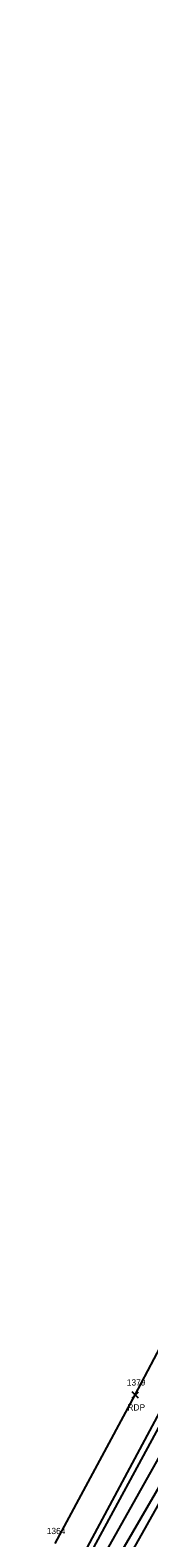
# Model space of a CAD drawing. Extents: x 1483143 to 1488182, y 802902 to 807581.
# Drawn here: x 1487393.8 to 1487426.2, y 805492.2 to 805974.5 of the extents above; entities that cross this region are included whole.
import ezdxf

# ---------------------------------------------------------------- set-up
doc = ezdxf.new("R2010")
doc.units = 0
for name, color, linetype in [('LELB', 7, 'Continuous'), ('P_A', 7, 'Continuous'), ('P_I', 7, 'Continuous'), ('P_TIC', 7, 'Continuous'), ('PET', 7, 'Continuous'), ('PSP', 7, 'Continuous')]:
    doc.layers.add(name, color=color, linetype=linetype)

msp = doc.modelspace()

# ---------------------------------------------------------------- linework, layer by layer
at = {"layer": 'LELB'}
for points in [[(1487406.66, 805485.41), (1487431.45, 805531.24), (1487454.84, 805575.74), (1487473.75, 805612.05), (1487489.43, 805642.37), (1487507.64, 805678.53), (1487524.82, 805711.39), (1487541.86, 805746.09), (1487557.67, 805776.44), (1487575.49, 805812.01), (1487597.52, 805857.93), (1487620.62, 805906.82), (1487641.85, 805951.94), (1487662.18, 805996.35), (1487684.09, 806043.93), (1487694.42, 806066.95), (1487726.58, 806140.7), (1487745.85, 806185.55), (1487769.04, 806237.65), (1487788.58, 806284.85), (1487808.3, 806333.26), (1487827.52, 806379.6), (1487850.09, 806437.73)], [(1487410.04, 805483.24), (1487436.07, 805529.53), (1487459.78, 805575.03), (1487477.42, 805609.67), (1487492.45, 805639.09), (1487509.86, 805677.27), (1487528.68, 805708.85), (1487545.3, 805744.17), (1487561.79, 805774.32), (1487579.7, 805810.21), (1487602.04, 805856.31), (1487624.97, 805905.57), (1487645.72, 805950.02), (1487667.21, 805993.1), (1487687.16, 806043.23), (1487699.2, 806065.16), (1487730.65, 806138.87), (1487749.96, 806183.58), (1487772.93, 806235.17), (1487792.36, 806283.08), (1487812.9, 806331.5), (1487831.61, 806378.23), (1487855.61, 806436.65)], [(1487413.83, 805481.53), (1487440.22, 805526.89), (1487464.36, 805572.85), (1487481.71, 805606.55), (1487496.63, 805636.25), (1487514.9, 805673.97), (1487535.8, 805705.94), (1487549.07, 805741.59), (1487566.17, 805772.22), (1487583.99, 805807.69), (1487605.26, 805855.28), (1487629.33, 805903.01), (1487650.26, 805948.76), (1487670.48, 805991.25), (1487690.28, 806041.74), (1487702.22, 806061.37), (1487704.47, 806066.39), (1487735.28, 806136.71), (1487754, 806182.42), (1487776.55, 806233.47), (1487796.75, 806281.41), (1487816.88, 806330.25), (1487835.19, 806376.59), (1487859.78, 806434.97)], [(1487417, 805480.8), (1487442.28, 805525.8), (1487466.47, 805571.82), (1487483.84, 805604.86), (1487498.25, 805635.76), (1487518.24, 805671.86), (1487538.47, 805704.77), (1487552.2, 805739.67), (1487568.17, 805771.84), (1487585.97, 805806.76), (1487609.39, 805853.47), (1487632.34, 805900.81), (1487653.02, 805947.32), (1487672.59, 805990.01), (1487694.92, 806039.27), (1487707.45, 806059.25), (1487710.05, 806064.3), (1487737.97, 806135.43), (1487757.4, 806181.42), (1487778.76, 806231.94), (1487799.97, 806279.97), (1487818.92, 806329.91), (1487837.5, 806376), (1487863.45, 806433.38)]]:
    msp.add_lwpolyline(points, dxfattribs=at)
at = {"layer": 'P_TIC'}
for points in [[(1487420.9, 805536.94), (1487422.9, 805538.94)], [(1487422.9, 805536.94), (1487420.9, 805538.94)]]:
    msp.add_lwpolyline(points, dxfattribs=at)
at = {"layer": 'PET'}
msp.add_lwpolyline([(1487396.33, 805490.41), (1487421.9, 805537.94), (1487444.13, 805580.16), (1487464.29, 805618.83), (1487479.8, 805648.39), (1487498.08, 805684.27), (1487514.57, 805717.15), (1487530.55, 805749.06), (1487547.16, 805782.47), (1487564.33, 805817.54), (1487585.71, 805863.32), (1487608.89, 805911.38), (1487630.35, 805956.68), (1487651.22, 806001.25), (1487672.63, 806048.33), (1487683.65, 806072.29), (1487715.61, 806144.47), (1487735.35, 806190.47), (1487757.48, 806241.03), (1487777.65, 806289.15), (1487798.25, 806337.46), (1487817.05, 806384.04), (1487839.67, 806441.4)], dxfattribs=at)
at = {"layer": 'PSP'}
msp.add_lwpolyline([(1487405.03, 805486.21), (1487429.8, 805532.42), (1487452.92, 805576.31), (1487472.37, 805613.24), (1487487.86, 805643.29), (1487506.35, 805679.4), (1487523.34, 805712.45), (1487540.38, 805746.64), (1487556.03, 805777.85), (1487573.44, 805813.27), (1487595.34, 805859.04), (1487618.37, 805906.67), (1487640.09, 805952.42), (1487660.18, 805997.21), (1487682.38, 806044.71), (1487693.04, 806068.56), (1487725.12, 806141.19), (1487744.39, 806185.87), (1487766.81, 806238.55), (1487786.8, 806285.64), (1487806.77, 806333.93), (1487825.55, 806380.21), (1487847.81, 806437.56)], dxfattribs=at)

# ---------------------------------------------------------------- texts
at = {"layer": 'P_A'}
msp.add_text('RDP', height=2, dxfattribs=at).set_placement((1487419.39, 805532.94))
at = {"layer": 'P_I'}
for s, p in [('1379', (1487419.2, 805540.94)), ('1364', (1487393.59, 805493.41))]:
    msp.add_text(s, height=2, dxfattribs=at).set_placement(p)

doc.saveas('drawing.dxf')
